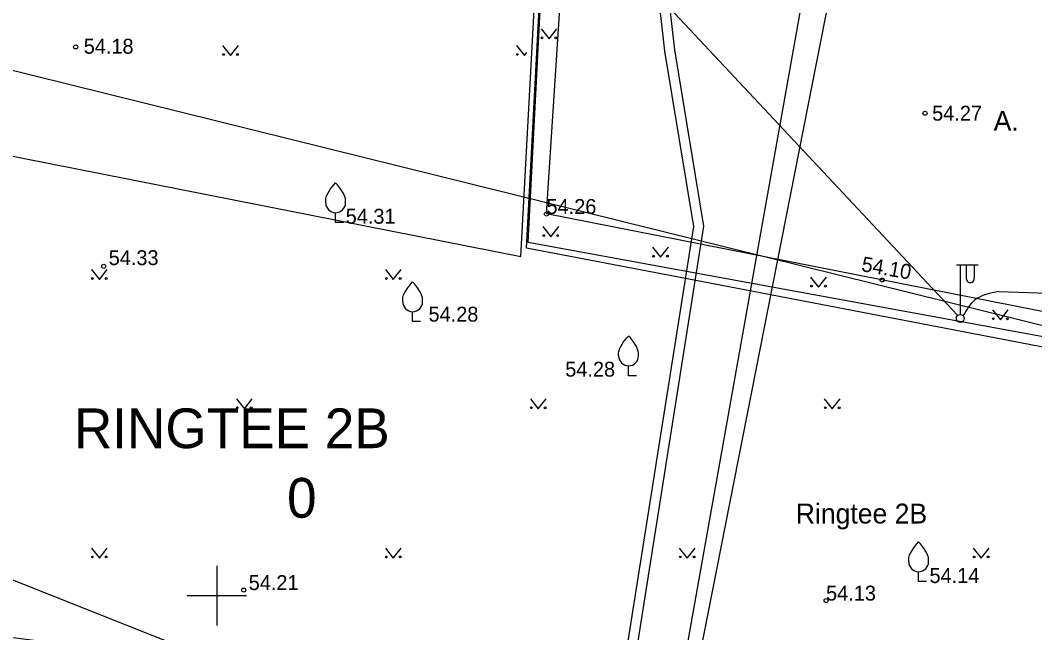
# Model space of a CAD drawing. Extents: x 9156 to 9809, y 2728 to 4000.
# Drawn here: x 9690.1 to 9741.2, y 3698.1 to 3728.9 of the extents above; entities that cross this region are included whole.
import ezdxf

# ---------------------------------------------------------------- set-up
doc = ezdxf.new("R2010")
doc.units = 0
for name, color, linetype in [('Level 1', 7, 'Continuous'), ('Level 17', 7, 'Continuous'), ('Level 5', 7, 'Continuous'), ('Level 54', 7, 'Continuous'), ('Level 56', 7, 'Continuous'), ('Level 7', 7, 'Continuous')]:
    doc.layers.add(name, color=color, linetype=linetype)

msp = doc.modelspace()

# ---------------------------------------------------------------- linework, layer by layer
at = {"layer": 'Level 1'}
msp.add_line((9518.632, 3768.823), (9760.318, 3708.94), dxfattribs=at)
msp.add_line((9518.632, 3768.823), (9760.318, 3708.94), dxfattribs=at)
at = {"layer": 'Level 17'}
msp.add_line((9685.405, 3702.503), (9713.644, 3691.304), dxfattribs=at)
at = {"layer": 'Level 54'}
for p, q in [((9715.664, 3717.757), (9721.689, 3832.211)), ((9722.553, 3727.38), (9721.115, 3740.531)), ((9721.688, 3683.648), (9732.75, 3739.763)), ((9721.741, 3738.725), (9723.035, 3727.46)), ((9719.649, 3674.847), (9730.614, 3736.312)), ((9737.267, 3714.117), (9717.846, 3734.851)), ((9716.318, 3728.509), (9716.721, 3728.004)), ((9716.721, 3728.004), (9717.118, 3728.509)), ((9700.282, 3727.669), (9700.682, 3727.166)), ((9700.682, 3727.166), (9701.082, 3727.669)), ((9715.08, 3727.669), (9715.481, 3727.166)), ((9723.035, 3727.46), (9724.506, 3718.575)), ((9723.035, 3727.46), (9724.506, 3718.575)), ((9715.481, 3727.166), (9715.598, 3727.314)), ((9724.011, 3718.574), (9722.553, 3727.38)), ((9705.978, 3718.762), (9705.978, 3719.262)), ((9706.378, 3718.762), (9705.978, 3718.762)), ((9716.408, 3718.559), (9716.811, 3718.054)), ((9716.811, 3718.054), (9717.208, 3718.559)), ((9717.216, 3675.691), (9724.011, 3718.574)), ((9724.506, 3718.575), (9717.413, 3673.886)), ((9760.645, 3709.542), (9715.664, 3717.757)), ((9721.929, 3717.521), (9722.332, 3717.015)), ((9722.332, 3717.015), (9722.729, 3717.521)), ((9693.683, 3716.399), (9694.084, 3715.896)), ((9694.084, 3715.896), (9694.483, 3716.399)), ((9708.482, 3716.399), (9708.883, 3715.896)), ((9708.883, 3715.896), (9709.282, 3716.399)), ((9737.227, 3716.644), (9738.327, 3716.644)), ((9737.427, 3716.644), (9737.427, 3714.144)), ((9737.727, 3716.644), (9737.727, 3715.944)), ((9738.127, 3716.644), (9738.127, 3715.944)), ((9729.886, 3716.016), (9730.289, 3715.511)), ((9730.289, 3715.511), (9730.686, 3716.016)), ((9739.367, 3715.288), (9770.072, 3714.274)), ((9709.856, 3713.781), (9709.856, 3714.281)), ((9739.042, 3714.372), (9739.445, 3713.867)), ((9739.445, 3713.867), (9739.842, 3714.372)), ((9710.256, 3713.781), (9709.856, 3713.781)), ((9720.727, 3711.056), (9720.727, 3711.556)), ((9721.127, 3711.056), (9720.727, 3711.056)), ((9700.983, 3709.896), (9701.384, 3709.392)), ((9701.384, 3709.392), (9701.783, 3709.896)), ((9715.782, 3709.896), (9716.183, 3709.392)), ((9716.183, 3709.392), (9716.582, 3709.896)), ((9730.58, 3709.896), (9730.981, 3709.392)), ((9730.981, 3709.392), (9731.38, 3709.896)), ((9693.683, 3702.39), (9694.084, 3701.886)), ((9694.084, 3701.886), (9694.483, 3702.39)), ((9708.482, 3702.39), (9708.883, 3701.886)), ((9708.883, 3701.886), (9709.282, 3702.39)), ((9723.28, 3702.39), (9723.681, 3701.886)), ((9723.681, 3701.886), (9724.08, 3702.39)), ((9738.079, 3702.39), (9738.479, 3701.886)), ((9738.479, 3701.886), (9738.879, 3702.39)), ((9700, 3701.5), (9700, 3698.5)), ((9700, 3701.5), (9700, 3698.5)), ((9735.329, 3700.7), (9735.329, 3701.2)), ((9735.729, 3700.7), (9735.329, 3700.7)), ((9698.5, 3700), (9701.5, 3700)), ((9698.5, 3700), (9701.5, 3700))]:
    msp.add_line(p, q, dxfattribs=at)
for points in [[(9722.811, 3716.105), (9715.582, 3717.472), (9720.877, 3817.559)], [(9762.185, 3706.838), (9761.899, 3708.198), (9761.872, 3708.168), (9761.309, 3709.17), (9760.395, 3710.143), (9756.61, 3711.63), (9744.711, 3713.671), (9744.494, 3712.557), (9743.325, 3712.733), (9743.586, 3713.889), (9716.595, 3719.196), (9717.559, 3733.926)], [(9705.478, 3719.762), (9705.478, 3719.912), (9705.488, 3719.977), (9705.526, 3720.105), (9705.582, 3720.229), (9705.728, 3720.462), (9705.888, 3720.667), (9705.978, 3720.762)], [(9706.478, 3719.762), (9706.478, 3719.912), (9706.469, 3719.977), (9706.431, 3720.105), (9706.375, 3720.229), (9706.228, 3720.462), (9706.068, 3720.667), (9705.978, 3720.762)], [(9669.366, 3700.509), (9706.561, 3695.721), (9760.177, 3687.877), (9760.263, 3708.241), (9757.403, 3709.459), (9722.811, 3716.105)], [(9709.356, 3714.781), (9709.356, 3714.931), (9709.365, 3714.996), (9709.403, 3715.125), (9709.459, 3715.248), (9709.606, 3715.481), (9709.765, 3715.686), (9709.856, 3715.781)], [(9710.356, 3714.781), (9710.356, 3714.931), (9710.346, 3714.996), (9710.308, 3715.125), (9710.252, 3715.248), (9710.106, 3715.481), (9709.946, 3715.686), (9709.856, 3715.781)], [(9720.227, 3712.056), (9720.227, 3712.206), (9720.236, 3712.271), (9720.274, 3712.399), (9720.33, 3712.523), (9720.477, 3712.756), (9720.637, 3712.961), (9720.727, 3713.056)], [(9721.227, 3712.056), (9721.227, 3712.206), (9721.217, 3712.271), (9721.179, 3712.399), (9721.123, 3712.523), (9720.977, 3712.756), (9720.817, 3712.961), (9720.727, 3713.056)], [(9734.829, 3701.7), (9734.829, 3701.85), (9734.839, 3701.915), (9734.876, 3702.043), (9734.932, 3702.167), (9735.079, 3702.4), (9735.239, 3702.605), (9735.329, 3702.7)], [(9735.829, 3701.7), (9735.829, 3701.85), (9735.819, 3701.915), (9735.781, 3702.043), (9735.725, 3702.167), (9735.579, 3702.4), (9735.419, 3702.605), (9735.329, 3702.7)]]:
    msp.add_lwpolyline(points, dxfattribs=at)
for centre, radius in [((9716.368, 3728.059), 0.0428), ((9717.068, 3728.059), 0.0452), ((9692.891, 3727.599), 0.102), ((9700.332, 3727.219), 0.0407), ((9701.032, 3727.219), 0.0486), ((9715.13, 3727.219), 0.0407), ((9735.648, 3724.262), 0.102), ((9716.595, 3719.196), 0.102), ((9716.458, 3718.109), 0.0428), ((9717.158, 3718.109), 0.0452), ((9721.979, 3717.071), 0.0428), ((9722.679, 3717.071), 0.0452), ((9694.306, 3716.561), 0.102), ((9693.733, 3715.949), 0.0433), ((9694.433, 3715.949), 0.0482), ((9708.532, 3715.949), 0.0433), ((9709.232, 3715.949), 0.0482), ((9733.491, 3715.873), 0.102), ((9729.936, 3715.566), 0.0428), ((9730.636, 3715.566), 0.0452), ((9737.427, 3713.944), 0.2), ((9739.092, 3713.922), 0.0428), ((9739.792, 3713.922), 0.0452), ((9701.033, 3709.446), 0.0407), ((9701.733, 3709.446), 0.0486), ((9715.832, 3709.446), 0.0407), ((9716.532, 3709.446), 0.0486), ((9730.63, 3709.446), 0.0407), ((9731.33, 3709.446), 0.0486), ((9693.733, 3701.94), 0.0433), ((9694.433, 3701.94), 0.0482), ((9708.532, 3701.94), 0.0433), ((9709.232, 3701.94), 0.0482), ((9723.33, 3701.94), 0.0433), ((9724.03, 3701.94), 0.0482), ((9738.129, 3701.94), 0.0433), ((9738.829, 3701.94), 0.0482), ((9701.351, 3700.275), 0.102), ((9730.668, 3699.747), 0.102)]:
    msp.add_circle(centre, radius, dxfattribs=at)
for centre, radius, start, end in [((9705.978, 3719.762), 0.5, 180, 0), ((9737.927, 3715.944), 0.2, 179.9393, 0.0607), ((9709.856, 3714.781), 0.5, 180, 0), ((9720.727, 3712.056), 0.5, 180, 0), ((9735.329, 3701.7), 0.5, 180, 0)]:
    msp.add_arc(centre, radius, start, end, dxfattribs=at)
msp.add_spline([(9739.367, 3715.288), (9738.16, 3714.873), (9737.569, 3714.086)], degree=3, dxfattribs=at)
at = {"layer": 'Level 56'}
msp.add_line((9685.405, 3702.503), (9713.644, 3691.304), dxfattribs=at)
at = {"layer": 'Level 7'}
for p, q in [((9715.31, 3717.05), (9716.77, 3744.61)), ((9674.54, 3725.09), (9715.31, 3717.05))]:
    msp.add_line(p, q, dxfattribs=at)

# ---------------------------------------------------------------- texts
at = {"layer": 'Level 5'}
for s, p in [('RINGTEE 2B', (9692.802, 3707.414)), ('0', (9703.533, 3703.914))]:
    msp.add_text(s, height=2, dxfattribs=at).set_placement(p)
at = {"layer": 'Level 54'}
for s, height, p in [('54.18', 0.75, (9693.297, 3727.258)), ('54.27', 0.75, (9736.009, 3723.892)), ('A.', 1, (9739.105, 3723.385)), ('54.26', 0.75, (9716.595, 3719.196)), ('54.31', 0.75, (9706.485, 3718.706)), ('54.33', 0.75, (9694.554, 3716.623)), ('54.28', 0.75, (9710.655, 3713.781)), ('54.28', 0.75, (9717.538, 3711.013)), ('Ringtee 2B', 1, (9729.143, 3703.624)), ('54.21', 0.75, (9701.601, 3700.275)), ('54.14', 0.75, (9735.876, 3700.63)), ('54.13', 0.75, (9730.668, 3699.747))]:
    msp.add_text(s, height=height, dxfattribs=at).set_placement(p)
msp.add_text('54.10', height=0.75, rotation=350.1101, dxfattribs=at).set_placement((9732.412, 3716.326))

doc.saveas('drawing.dxf')
